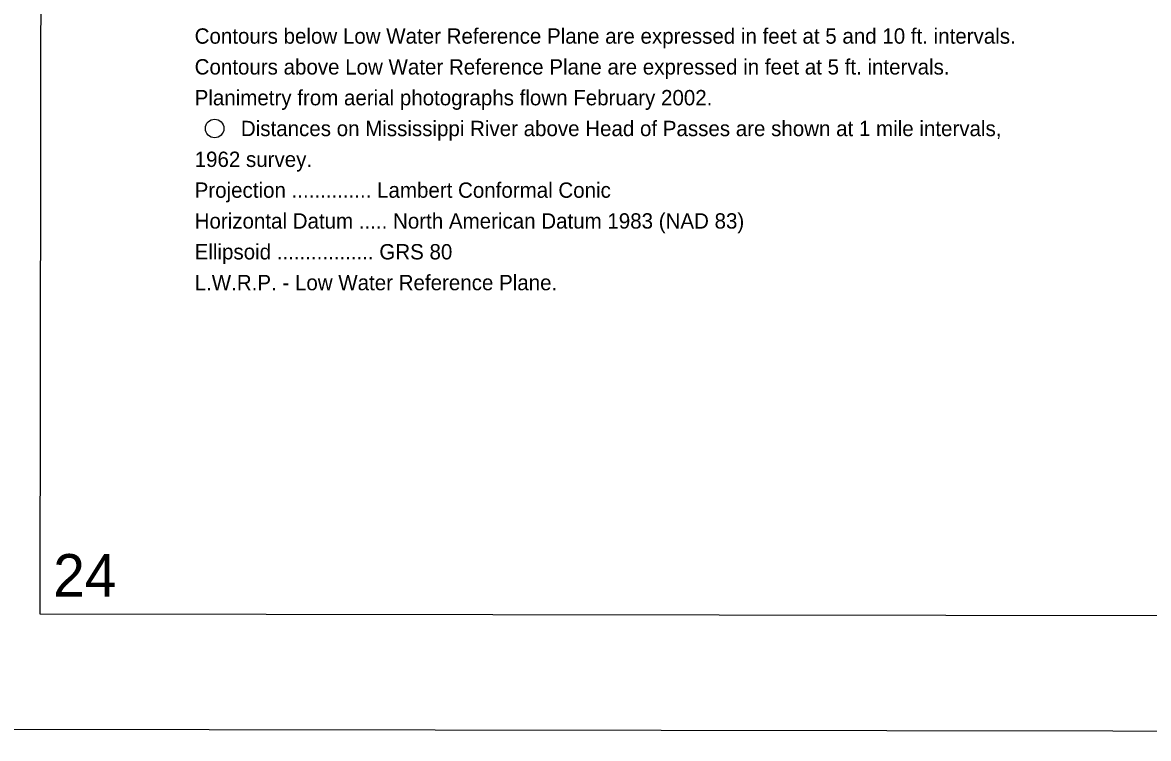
# Model space of a CAD drawing. Extents: x 3313442 to 3351311, y 721974 to 747360.
# Drawn here: x 3316683 to 3322775, y 722557 to 726429 of the extents above; entities that cross this region are included whole.
import ezdxf

# ---------------------------------------------------------------- set-up
doc = ezdxf.new("R2010")
doc.units = 0
for name, color, linetype in [('G-ANNO-NPLT', 7, 'Continuous'), ('V-ANNO-NOTE', 7, 'Continuous'), ('V-ANNO-SYMB', 7, 'Continuous'), ('V-ANNO-TEXT', 7, 'Continuous')]:
    doc.layers.add(name, color=color, linetype=linetype)

msp = doc.modelspace()

# ---------------------------------------------------------------- linework, layer by layer
at = {"layer": 'G-ANNO-NPLT'}
msp.add_lwpolyline([(3314025.4, 722610.3), (3350692.1, 722557), (3350727.2, 746723.6), (3314060.6, 746776.9)], close=True, dxfattribs=at)
at = {"layer": 'V-ANNO-NOTE'}
msp.add_circle((3317722.6, 725856.3), 50, dxfattribs=at)
at = {"layer": 'V-ANNO-SYMB'}
msp.add_lwpolyline([(3316776.5, 723231.3), (3349859.6, 723183.2), (3349893, 746099.8), (3316809.8, 746147.9), (3316776.5, 723231.3)], dxfattribs=at)

# ---------------------------------------------------------------- texts
at = {"layer": 'V-ANNO-NOTE'}
for s, rotation, p in [('Contours below Low Water Reference Plane are expressed in feet at 5 and 10 ft. intervals.', 0.00001, (3317614.4, 726314.9)), ('Contours above Low Water Reference Plane are expressed in feet at 5 ft. intervals.', 0.00001, (3317614.4, 726148.2)), ('Planimetry from aerial photographs flown February 2002.', 0.00001, (3317614.4, 725981.5)), ('Distances on Mississippi River above Head of Passes are shown at 1 mile intervals,', 0.00001, (3317864.6, 725814.8)), ('1962 survey.', 0.00001, (3317614.4, 725648.1)), ('Projection .............. Lambert Conformal Conic', 359.99998, (3317614.4, 725481.4)), ('Horizontal Datum ..... North American Datum 1983 (NAD 83)', 359.99998, (3317614.4, 725314.7)), ('Ellipsoid ................. GRS 80', 359.99998, (3317614.4, 725148)), ('L.W.R.P. - Low Water Reference Plane.', 359.99998, (3317614.4, 724981.3))]:
    msp.add_text(s, height=83, rotation=rotation, dxfattribs=at).set_placement(p)
at = {"layer": 'V-ANNO-TEXT'}
msp.add_text('24', height=230, rotation=359.91672, dxfattribs=at).set_placement((3316849.1, 723324.5))

doc.saveas('drawing.dxf')
